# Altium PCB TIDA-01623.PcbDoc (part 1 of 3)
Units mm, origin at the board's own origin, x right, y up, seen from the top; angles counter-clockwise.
Board outline 77.73 x 42 mm, 4 copper layers (Top Layer, Signal Layer 1, Signal Layer 2, Bottom Layer), stack 0.651 mm thick; 213 components, 127 nets, 575 pads, 342 vias.
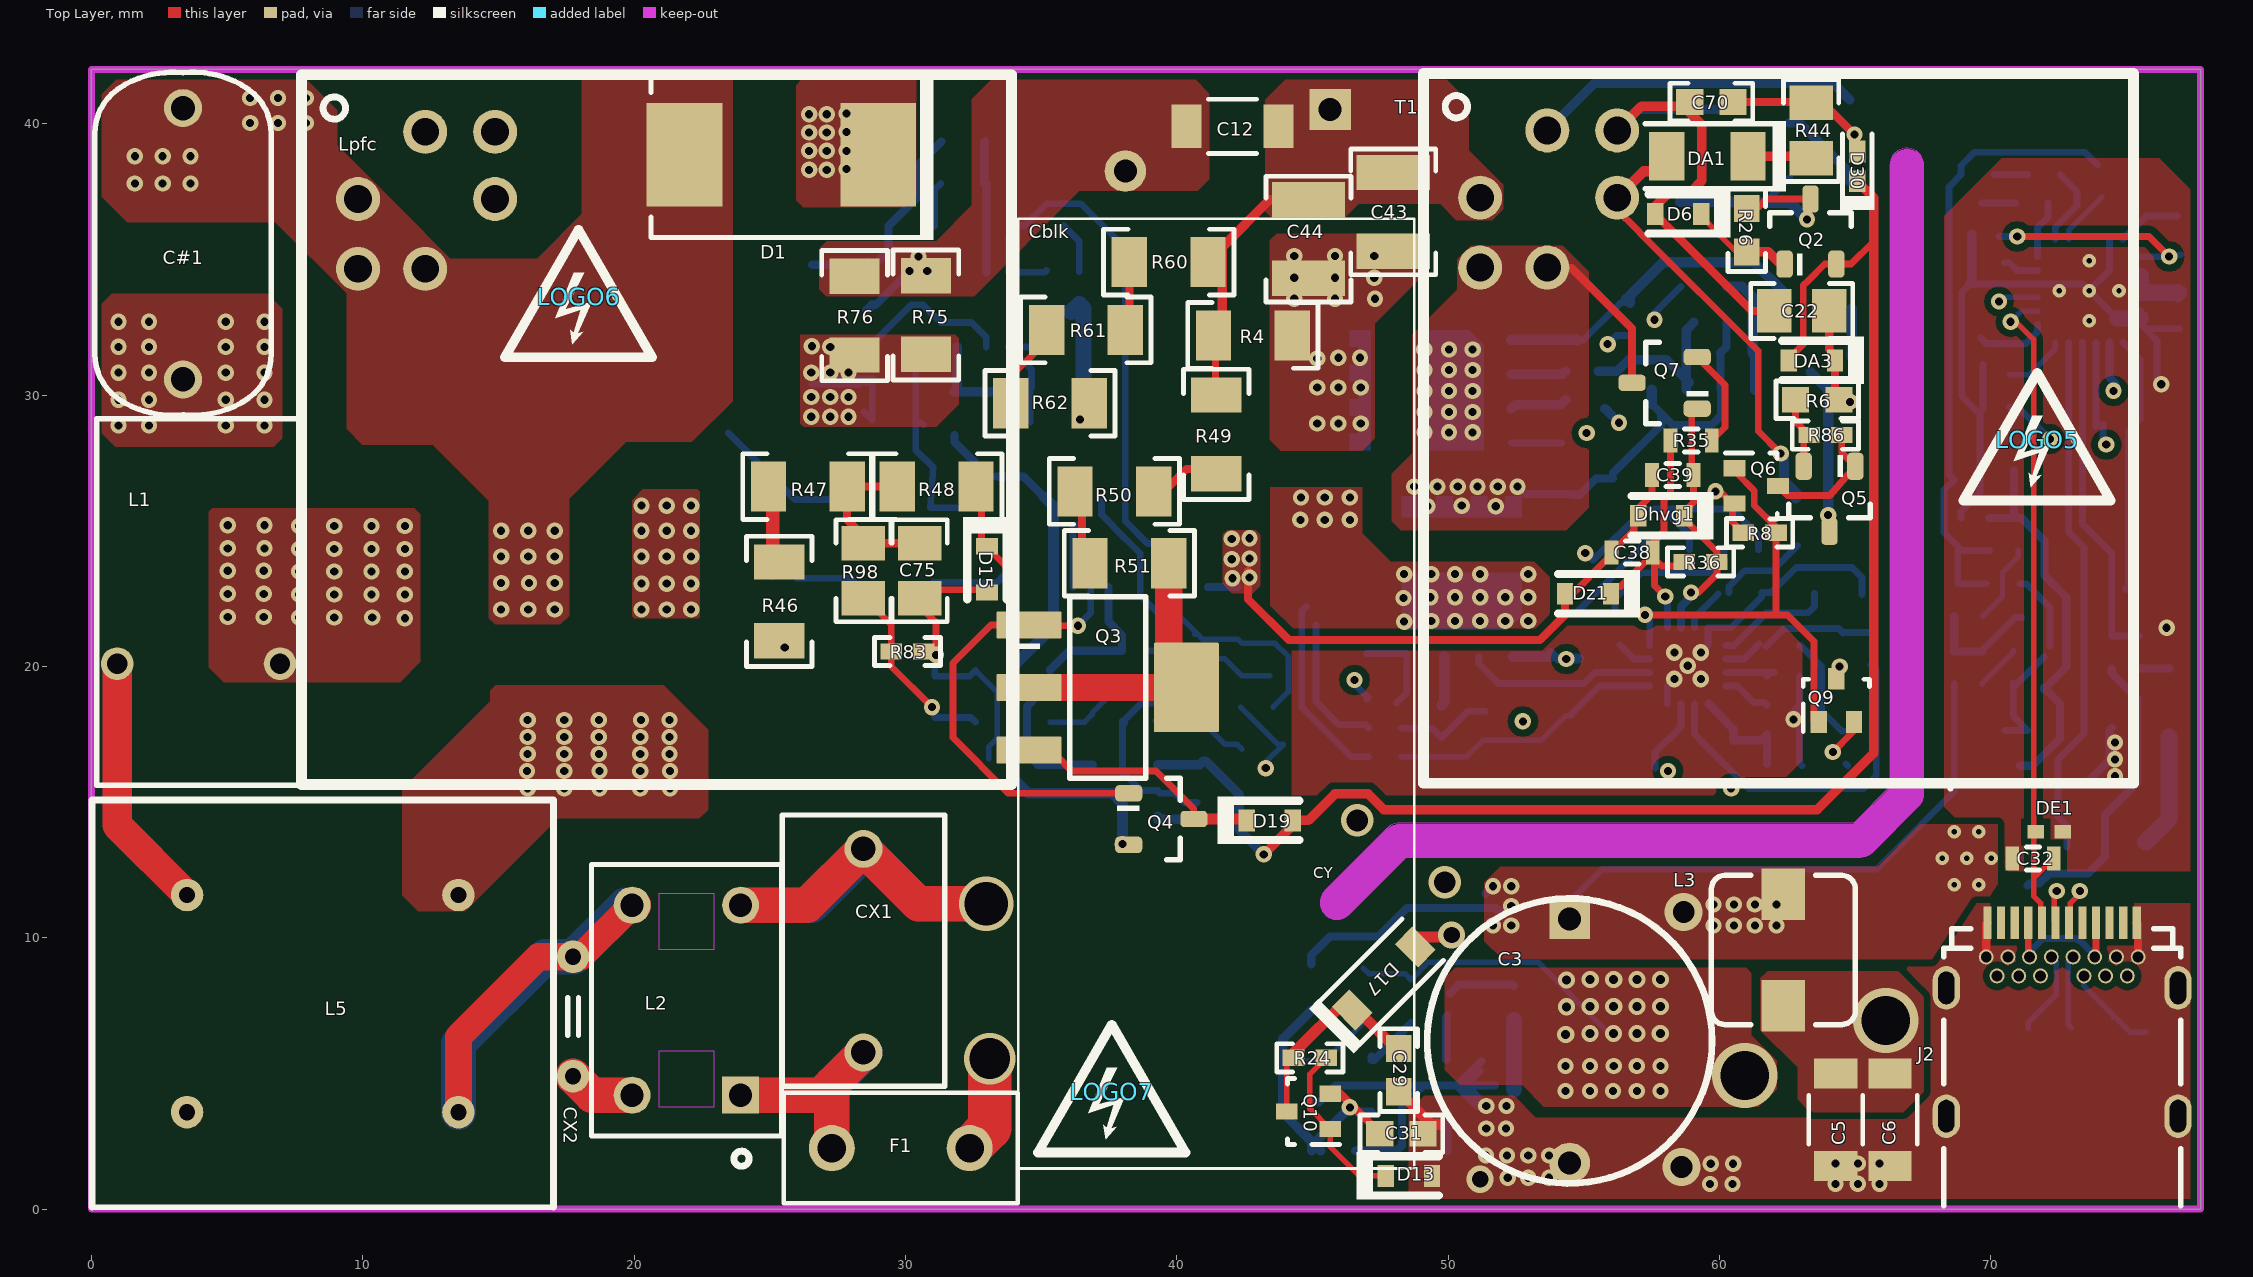
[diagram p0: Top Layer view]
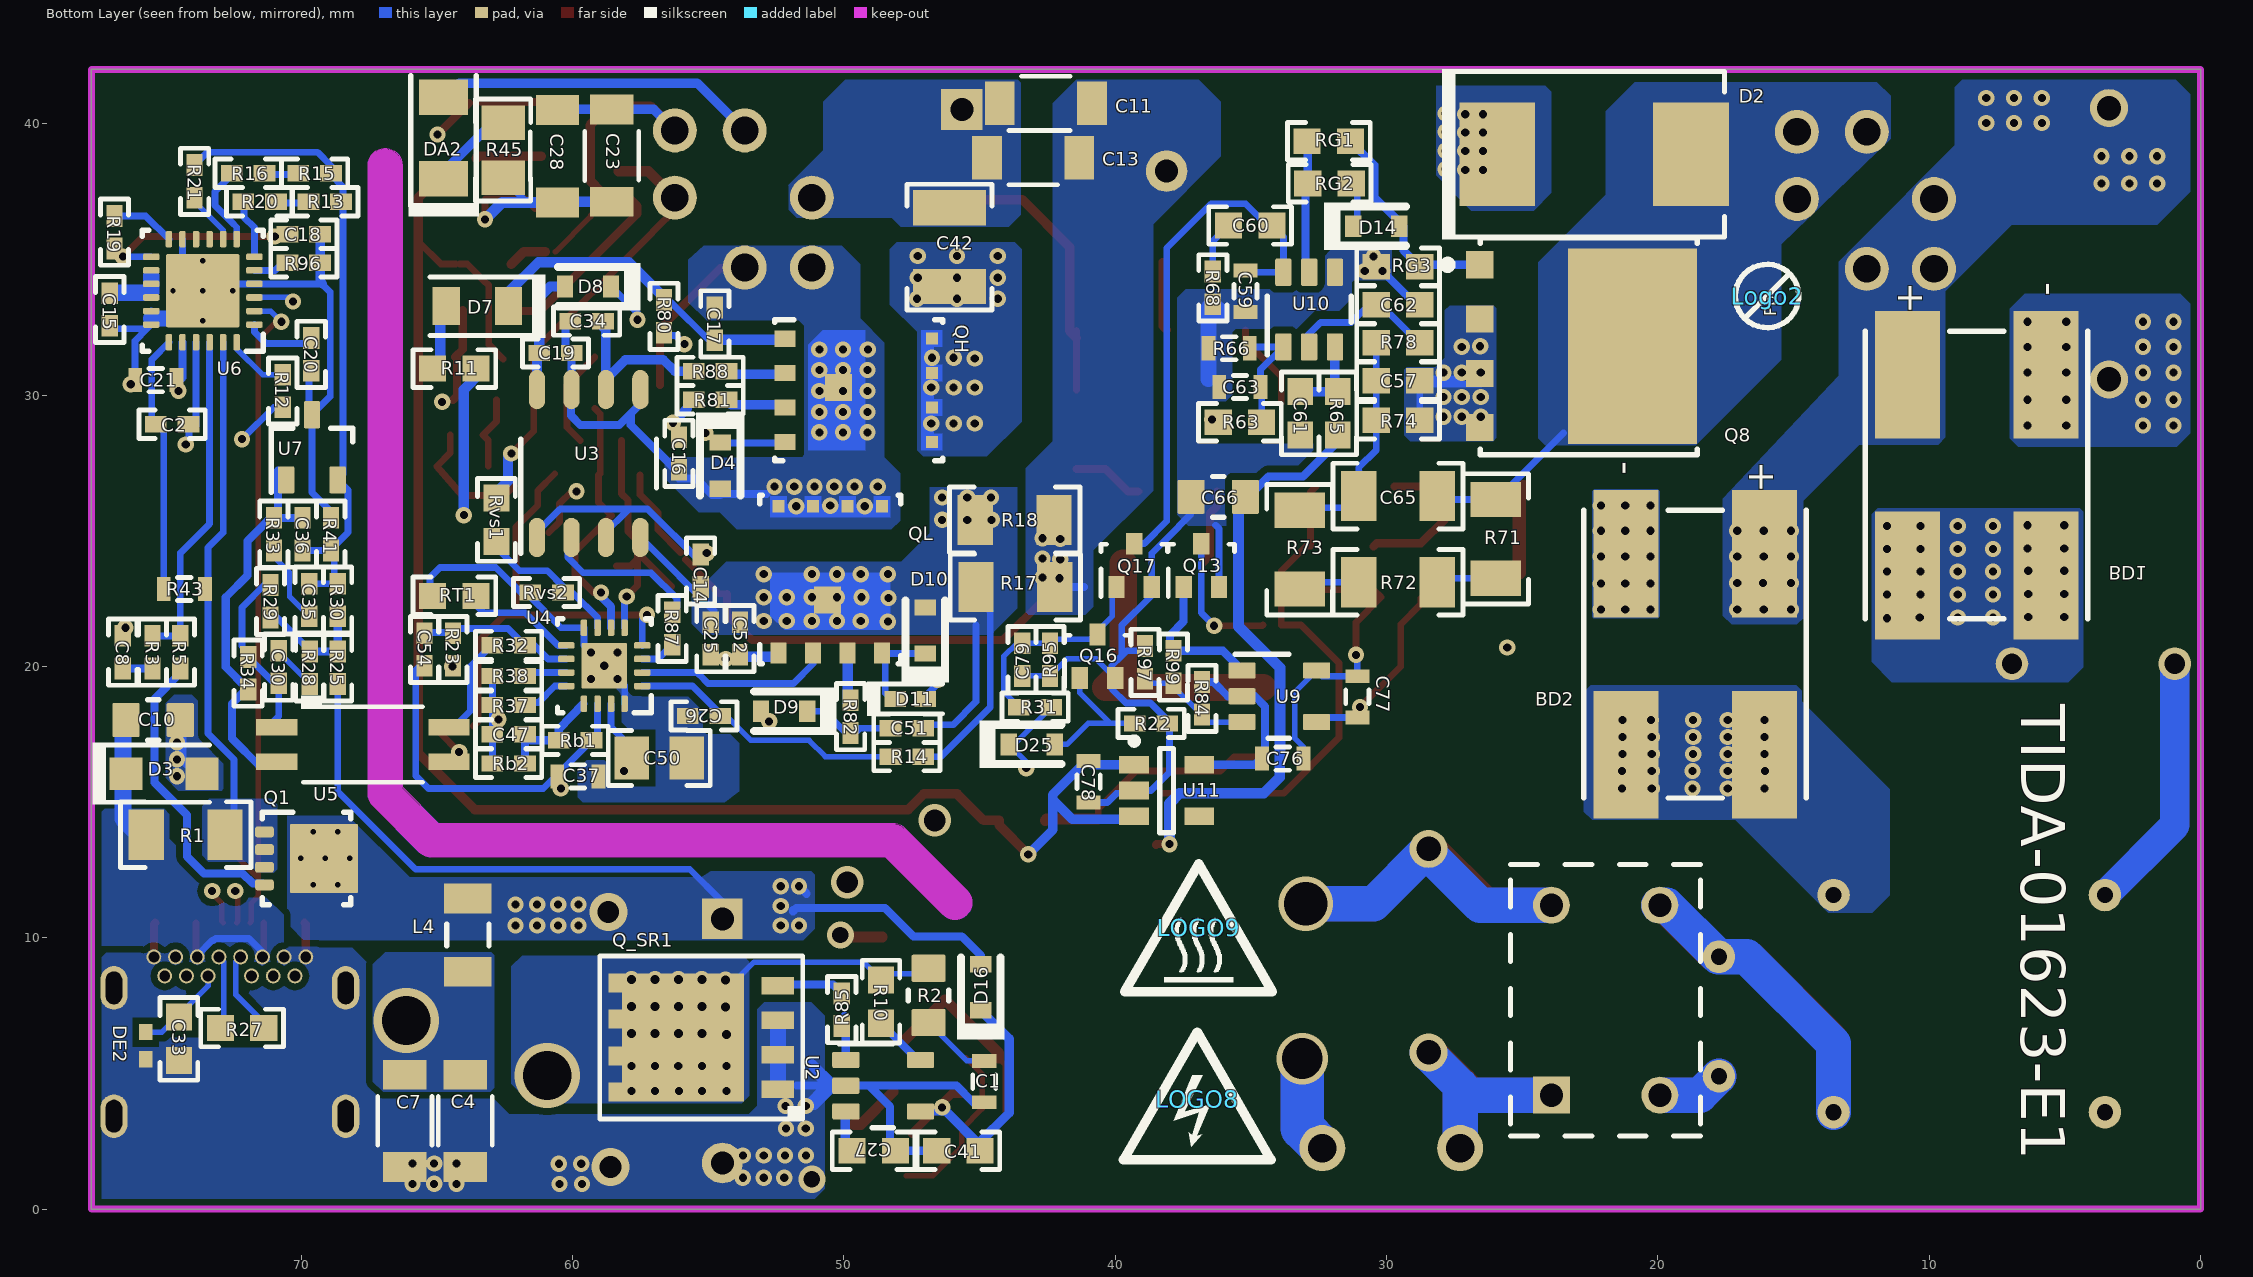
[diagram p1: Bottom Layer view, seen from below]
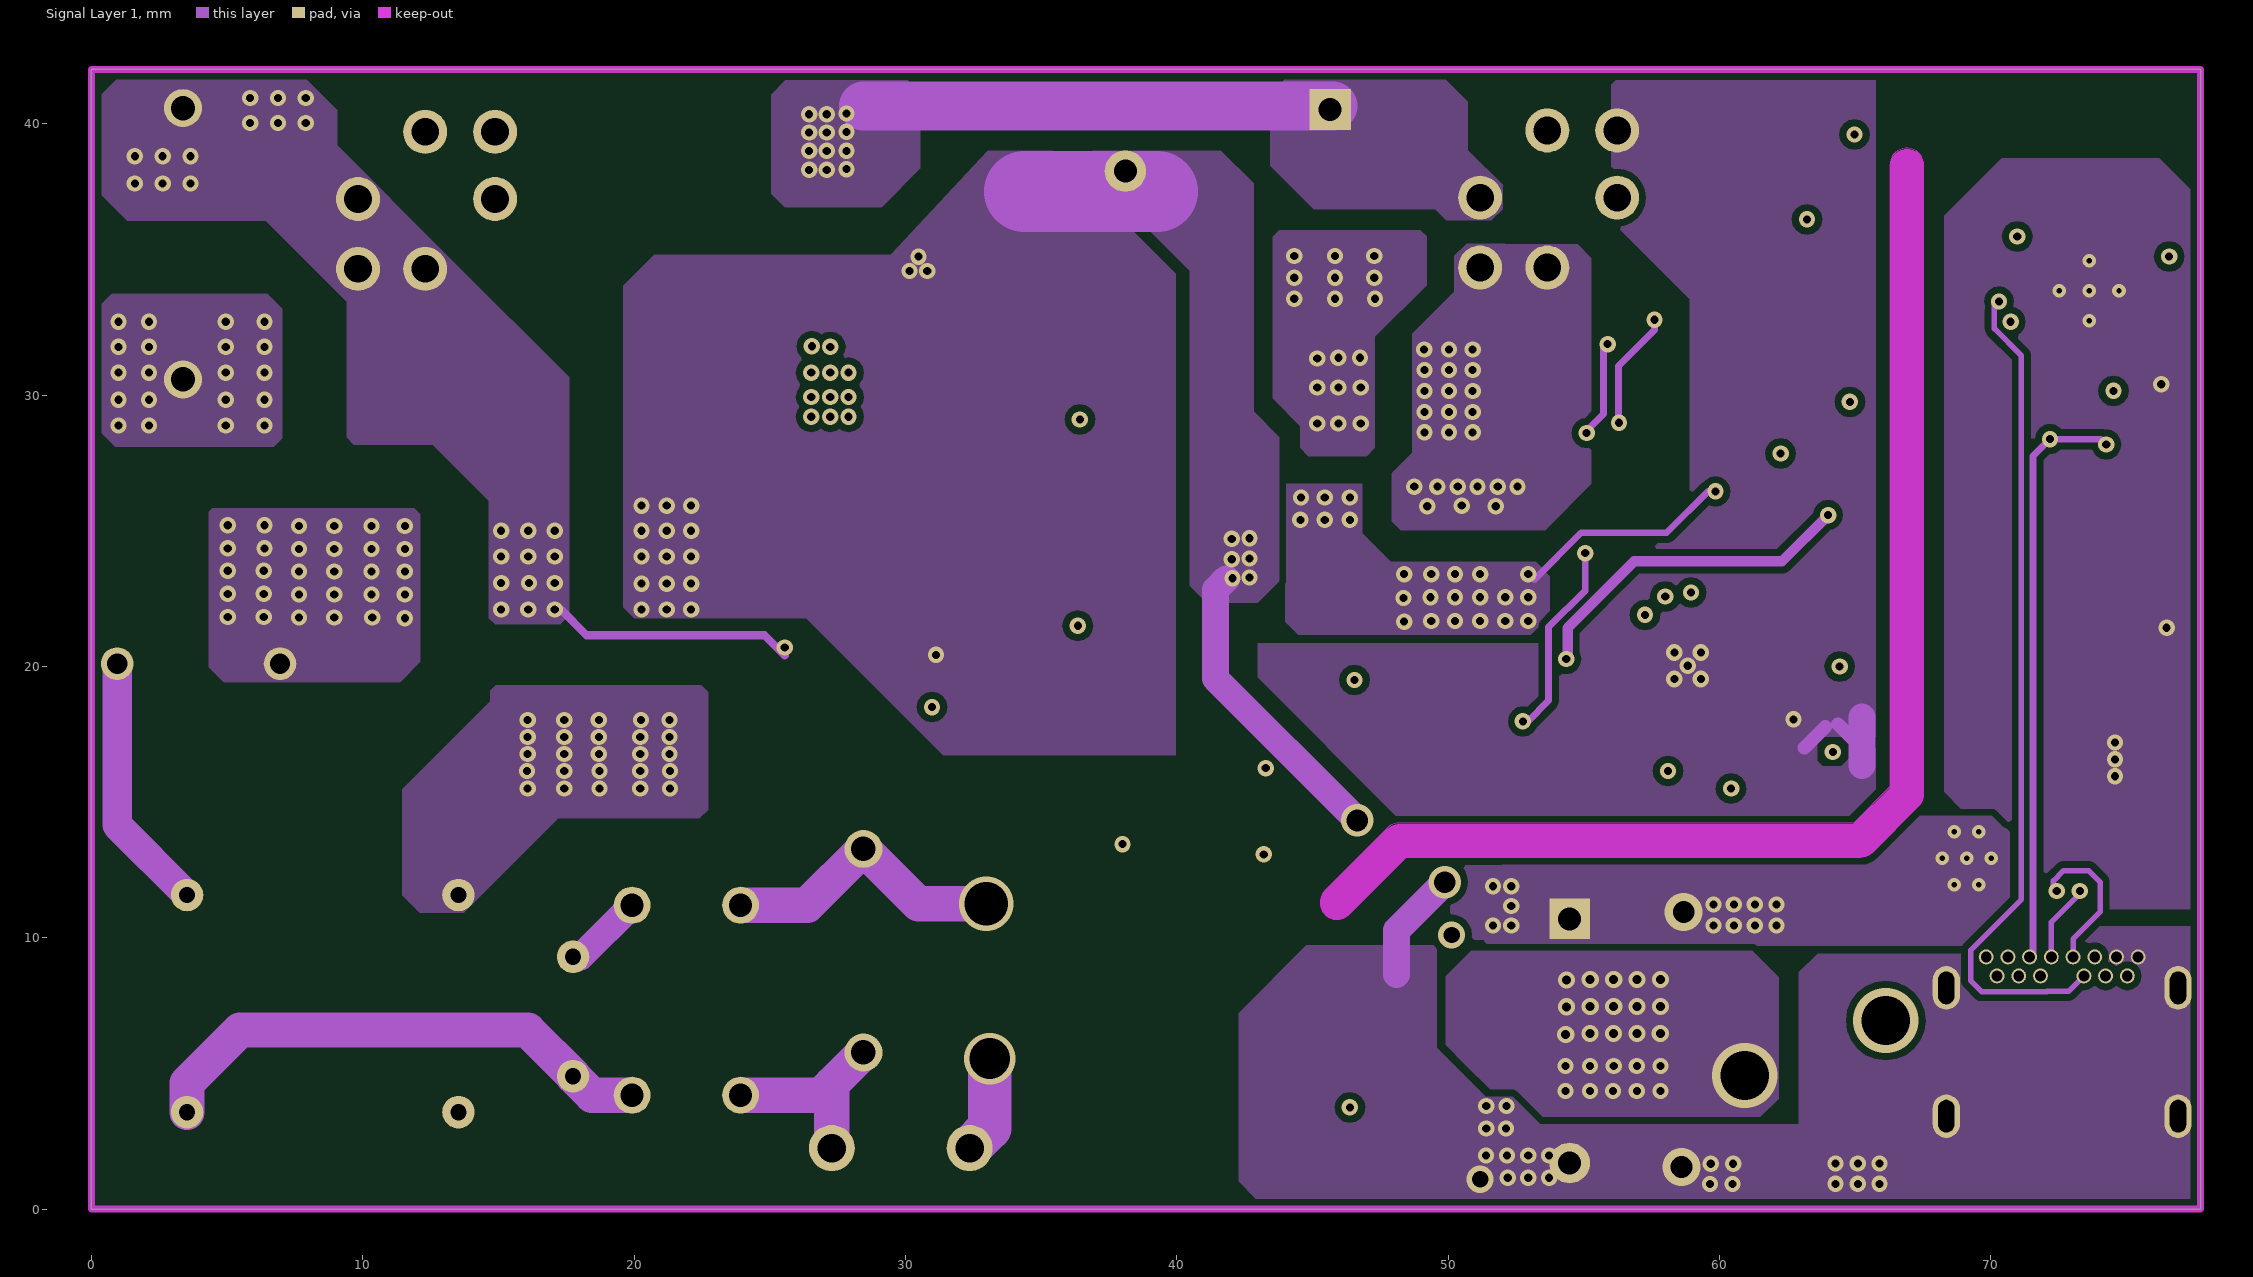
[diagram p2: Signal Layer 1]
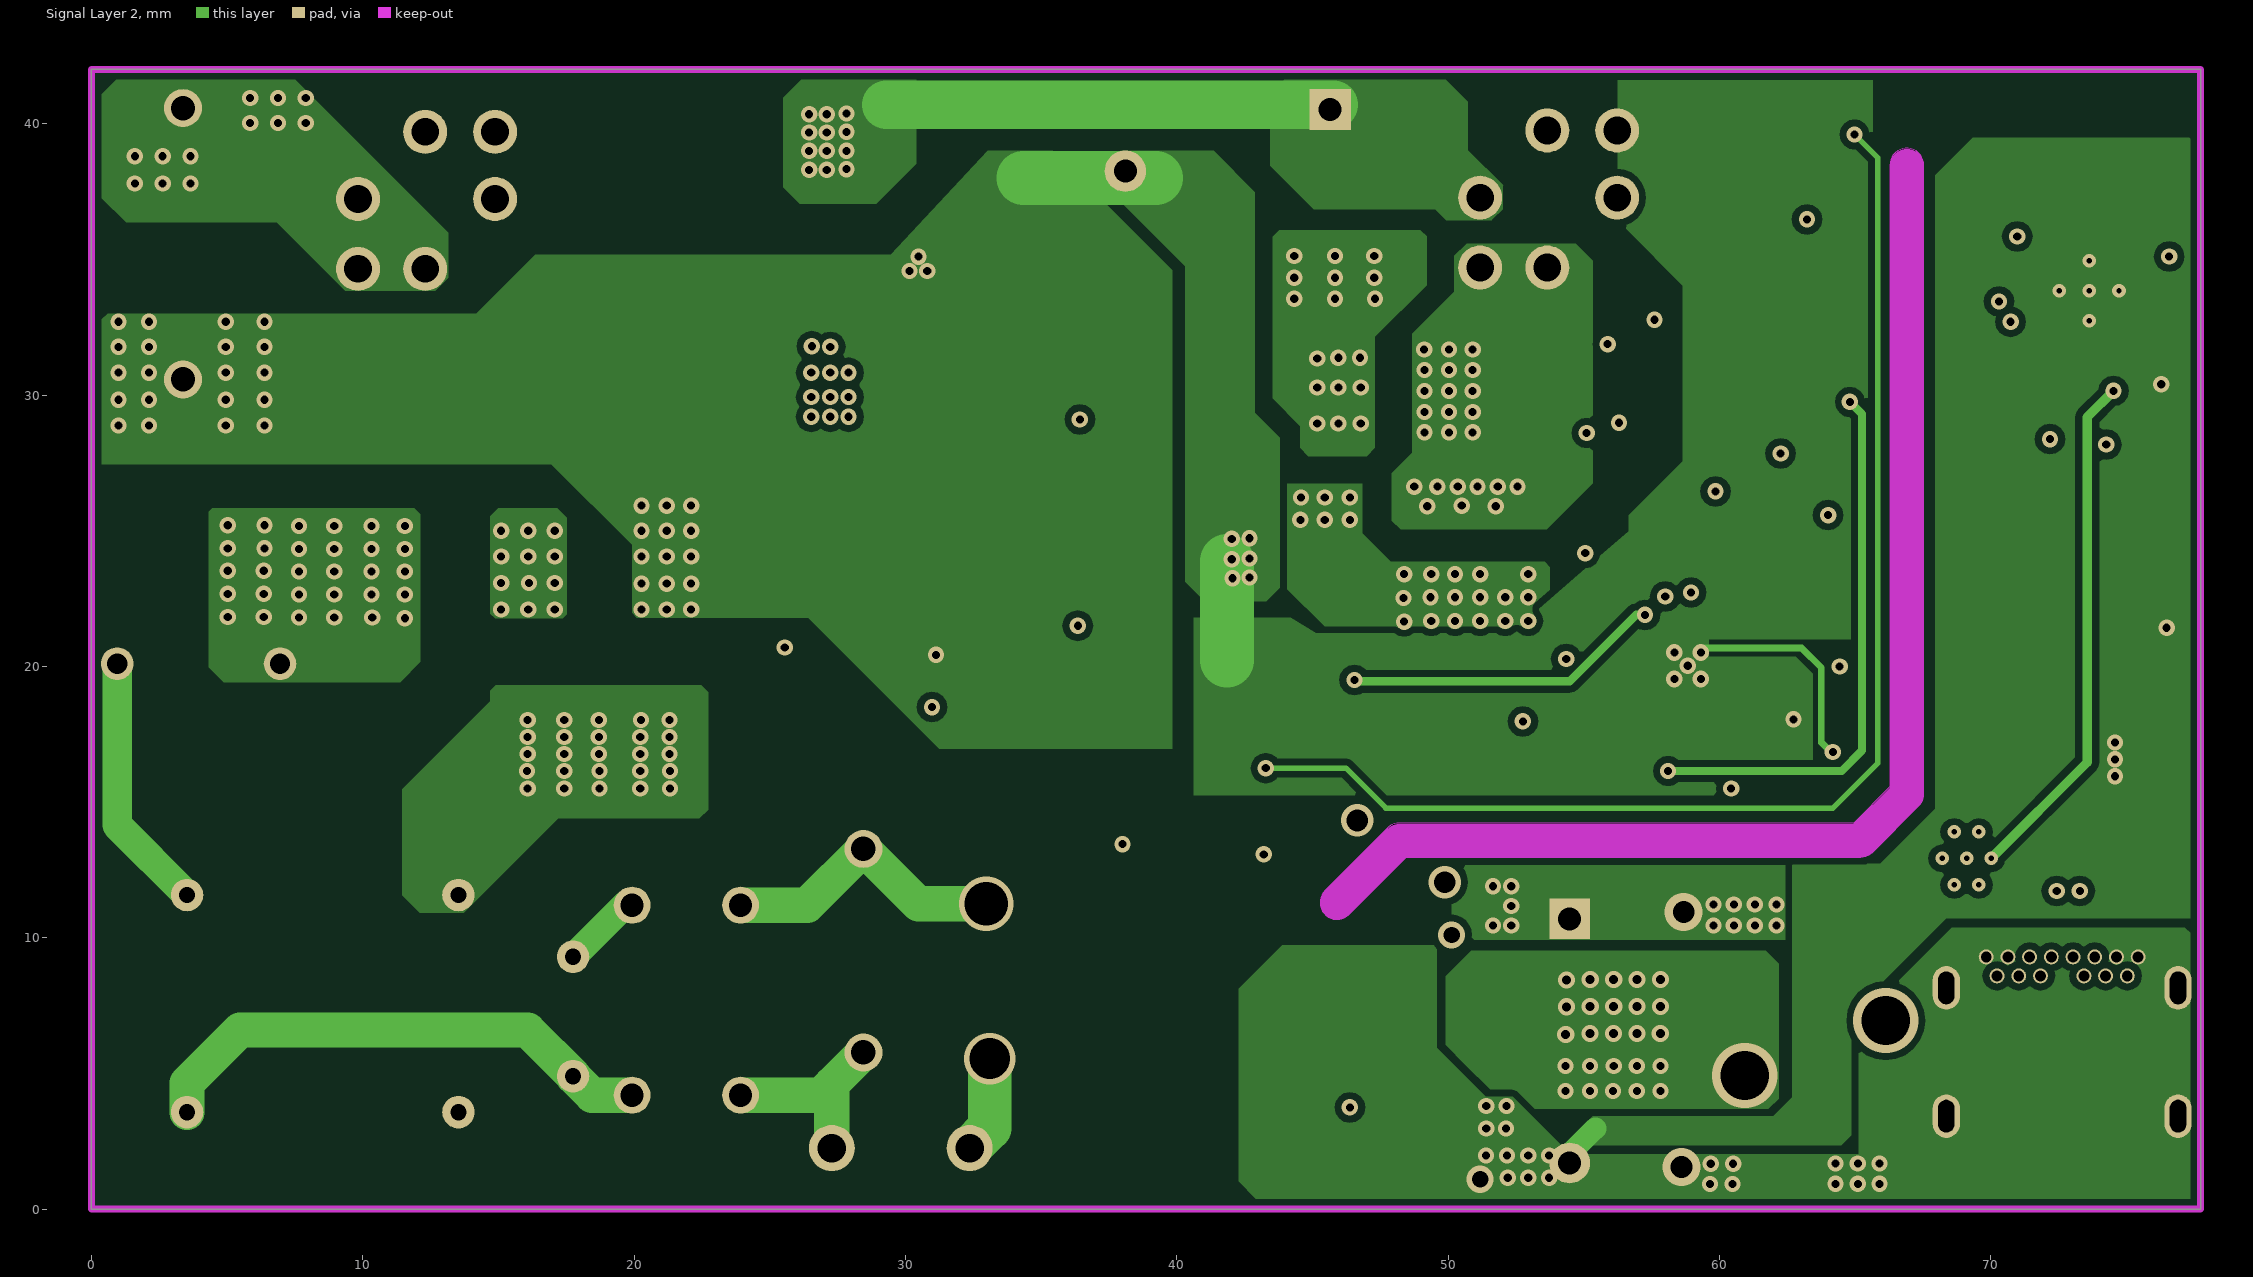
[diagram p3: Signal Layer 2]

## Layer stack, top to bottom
Top Solder: solder mask 0.0102, Solder Resist, Dk 3.5
Top Layer: signal copper 0.0356
Dielectric 1: prepreg 0.127, Dk 4.2
Signal Layer 1: signal copper 0.036
Dielectric 2: core 0.254, Dk 4.2
Signal Layer 2: signal copper 0.036
Dielectric 3: prepreg 0.127, Dk 4.2
Bottom Layer: signal copper 0.0356
Bottom Solder: solder mask 0.0102, Solder Resist, Dk 3.5

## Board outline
0,0 0,42 77.725,42 77.725,0
cut-out: 45.457,11.742 ccw(c45.9,11.3) 46.342,10.858 48.459,12.975 65.2,12.975 ccw(c65.2,13.6) 65.642,13.158 67.342,14.858 ccw(c66.9,15.3) 67.525,15.3 67.525,38.475 ccw(c66.9,38.475) 66.274,38.475 66.274,15.559 64.941,14.225 48.2,14.225 ccw(c48.2,13.6) 47.757,14.042

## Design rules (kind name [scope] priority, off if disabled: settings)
AcuteAngle [All] p1: minimum=4.50000000000000E+0001 checktracksonly=FALSE
AssemblyTestPointUsage [All] p1: valid=2
BoardOutlineClearance BoardOutlineClearance_MountingHoles [OnCopper and InComponentClass('Mounting Holes')] p1: gap=0.3
BoardOutlineClearance BoardOutlineClearance_Poly [OnCopper and IsPoly] p2: gap=0.3
BoardOutlineClearance [OnCopper and Not InComponentClass('Logo') and not InComponentClass('FiducialMark') and not InRegion(1000,500,4000,800) and not InPoly] p3: gap=0.3
Clearance Clearance_Keepouts [((IsTrack Or IsArc) And Not InPoly) And IsFree and IsKeepOut vs ((IsTrack Or IsArc) And Not InPoly) And IsFree and IsKeepOut] p1: gap=0.254
Clearance Clearance_Poly [InPolygon] p2: gap=0.254
Clearance [All] p3: gap=0.2
ComponentClearance ComponentClearance_MountingHoles_FiducialMarks [InComponentClass('Mounting Holes') vs InComponentClass('FiducialMark')] p1 off: gap=0.1 collisioncheckmode=3 verticalgap=0.1 showdistances=FALSE
ComponentClearance ComponentClearance_Shunt [InComponentClass('Header') vs InComponentClass('Shunt')] p2 off: gap=0 collisioncheckmode=3 verticalgap=0 showdistances=FALSE
ComponentClearance ComponentClearance_Logo [InComponentClass('Logo')] p3 off: gap=0.1 collisioncheckmode=3 verticalgap=0.1 showdistances=FALSE
ComponentClearance ComponentClearance_ScrewToNut [(HasFootprint('NY PMS 440 0025 PH')) vs (HasFootprint('Keystone_1902C'))] p4 off: gap=0.1 collisioncheckmode=3 verticalgap=0.1 showdistances=FALSE
ComponentClearance ComponentClearance_MountingHoles [InComponentClass('Mounting Holes')] p5 off: gap=0.1 collisioncheckmode=3 verticalgap=2540 showdistances=FALSE
ComponentClearance ComponentClearance_SmallPassives [HasFootprint('0201*') or HasFootprint('0402*') or HasFootprint('0508') or HasFootprint('0603*') or HasFootprint('0612') or HasFootprint('0805*') or HasFootprint('0815*') or HasFootprint('0830*') or HasFootprint('1206*') or HasFootprint('1210*') or HasFootprint('1808*') or HasFootprint('1812*') or HasFootprint('1825*') or HasFootprint('2010*') or HasFootprint('2220*') or HasFootprint('2225*') or HasFootprint('2512*') or HasFootprint('2728*') or HasFootprint('3518*') vs HasFootprint('0201*') or HasFootprint('0402*') or HasFootprint('0508') or HasFootprint('0603*') or HasFootprint('0612') or HasFootprint('0805*') or HasFootprint('0815*') or HasFootprint('0830*') or HasFootprint('1206*') or HasFootprint('1210*') or HasFootprint('1808*') or HasFootprint('1812*') or HasFootprint('1825*') or HasFootprint('2010*') or HasFootprint('2220*') or HasFootprint('2225*') or HasFootprint('2512*') or HasFootprint('2728*') or HasFootprint('3518*')] p6 off: gap=0.1 collisioncheckmode=3 verticalgap=0.1 showdistances=FALSE
ComponentClearance ComponentClearance_THtoSMT [IsThruComponent vs IsSMTComponent] p7 off: gap=0.1 collisioncheckmode=3 verticalgap=0.1 showdistances=FALSE
ComponentClearance ComponentClearance_THtoTH [IsThruComponent vs IsThruComponent] p8 off: gap=0.1 collisioncheckmode=3 verticalgap=0.1 showdistances=FALSE
ComponentClearance [All] p9 off: gap=0.1 collisioncheckmode=3 verticalgap=0.1 showdistances=FALSE
DiffPairsRouting [All] p1: maxlimit=2.54 minlimit=0.254 mostfreqgap=0.254 toplayer_minwidth=0.381 toplayer_maxwidth=0.381 toplayer_prefwidth=0.381 midlayer1_minwidth=0.381 midlayer1_maxwidth=0.381 midlayer1_prefwidth=0.381 midlayer2_minwidth=0.381 midlayer2_maxwidth=0.381 midlayer2_prefwidth=0.381 bottomlayer_minwidth=0.381 bottomlayer_maxwidth=0.381 bottomlayer_prefwidth=0.381 maxuncoupledlength=25.4
FabricationTestPointUsage TestPointUsage [All] p1: valid=2 allowmultiple=FALSE
FabricationTestpoint Testpoint [All] p1: side=3 testpointundercomponent=TRUE minsize=1.016 maxsize=2.54 preferedsize=1.524 minholesize=0 maxholesize=1.016 preferedholesize=0.813 testpointgrid=0.025 allowsidetop=TRUE allowsidebottom=TRUE usegrid=TRUE gridtolerance=0
FanoutControl Fanout_LCC [IsLCC] p1: bgadir=Out bgaviamode=Centered fanoutstyle=Auto fanoutdirection=Alternating viagrid=0.025 // Fanout_LCC (Default Rule)
FanoutControl Fanout_BGA [IsBGA] p2: bgadir=Out bgaviamode=Centered fanoutstyle=Auto fanoutdirection=Alternating viagrid=0.025 // Fanout_BGA (Default Rule)
FanoutControl Fanout_Default [All] p4: bgadir=Out bgaviamode=Centered fanoutstyle=Auto fanoutdirection=Alternating viagrid=0.025 // Fanout_Default (Default Rule)
FanoutControl Fanout_Small [(CompPinCount < 5)] p5: bgadir=Out bgaviamode=Centered fanoutstyle=Auto fanoutdirection=OutThenIn viagrid=0.025 // Fanout_Small (Default Rule)
HoleSize [All] p1: absolutevalues=TRUE maxlimit=0.3 minlimit=0.3 maxpercent=80.000 minpercent=20.000
MinimumAnnularRing MinimumAnnularRing_ThermalPadVias [IsVia and InAnyComponent] p1: minimumring=0.15
MinimumAnnularRing [All] p2: minimumring=0.025
MinimumSolderMaskSliver MinimumSolderMaskSliver_Logo [InComponentClass('Logo') vs InComponentClass('Logo')] p1: minsoldermaskwidth=0.018
MinimumSolderMaskSliver [All] p2: minsoldermaskwidth=0.1
PlaneClearance [All] p1: clearance=0.254
PlaneConnect [All] p1: planeconnectstyle=Direct reliefexpansion=0.254 reliefentries=4 reliefconductorwidth=0.254 reliefairgap=0.254
PolygonConnect [All] p1: connectstyle=Direct reliefconductorwidth=0.254 reliefentries=4 polygonreliefangle="90 Angle" airgapwidth=0.254
RoutingVias ThermalPadVias [IsVia and InAnyComponent] p1: holewidth=0.2 width=0.5 viastyle="Through Hole" minholewidth=0.2 minwidth=0.5 maxholewidth=0.33 maxwidth=0.6
RoutingVias [All] p2: holewidth=0.3 width=0.6 viastyle="Through Hole" minholewidth=0.3 minwidth=0.6 maxholewidth=2 maxwidth=3
SilkToBoardRegionClearance [Not ((IsComment or IsDesignator) And (Hide <> 'False')) and not InRegion(1000,500,4000,800)] p1:
SilkToSilkClearance SilkToSilkClearance_Pb-FreeLogo [(HasFootprint('Pb-Free_Overlay_Medium') OR HasFootprint('Pb-Free_Overlay_Small')) vs (HasFootprint('Pb-Free_Overlay_Medium') OR HasFootprint('Pb-Free_Overlay_Small'))] p1: silktosilkclearance=0
SilkToSilkClearance [All] p2: silktosilkclearance=0.102
SilkToSolderMaskClearance SilkToComponentPadClearance [(IsPad or IsFill or IsRegion) and InAnycomponent] p1: minsilkscreentomaskgap=0.127 clearancetoexposedcopper=TRUE
SilkToSolderMaskClearance "Silk to Solder Mask Opening" [All] p2: minsilkscreentomaskgap=0.102 clearancetoexposedcopper=FALSE
SolderMaskExpansion [All] p1: expansion=0.05
Width [All] p1: maxlimit=2.54 minlimit=0.152 preferedwidth=0.254 checkconnectedcopper=TRUE
14 further rules are at their usual default settings.

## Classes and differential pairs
component class TIDA-01623_PFC_Stage: BD1 BD2 C56 C57 C59 C60 C61 C62 C63 C65 C66 C75 C76 C77 C78 C79 C#1 Cblk CX1 CX2 D1 D2 D14 D15 D19 D25 F1 L1 L2 L5 Lpfc Q3 Q4 Q8 Q13 Q16 Q17 R22 R31 R46 R47 R48 R49 R50 R51 R60 R61 R62 R63 R65 R66 R68 R71 R72 R73 R74 R75 R76 R78 R83 R84 R95 R97 R98 R99 RG1 RG2 RG3 U9 U10 U11
component class TIDA-01623_Hardware: !PCB1 Logo2 LOGO5 LOGO6 LOGO7 LOGO8 LOGO9 LOGO10
component class TIDA-01623-ACF_Stage: C1 C2 C3 C4 C5 C6 C7 C8 C10 C11 C12 C13 C14 C15 C16 C17 C18 C19 C20 C21 C22 C23 C25 C26 C27 C28 C29 C30 C31 C32 C33 C34 C35 C36 C37 C38 C39 C41 C42 C43 C44 C47 C50 C51 C52 C54 C70 D3 D4 D5 D6 D7 D8 D9 D10 D11 D13 D16 D17 D30 DA1 DA2 DA3 DE1 DE2 Dhvg1 Dz1 J2 L3 L4 Q1 Q2 Q5 Q6 Q7 Q9 Q10 Q_SR1 QH QL R1 R2 R3 R4 R5 R6 R8 R10 R11 R12 R13 R14 R15 R16 R17 R18 R19 R20 R21 R23 R24 R25 R26 R27 R28 R29 R30 R32 R33 R34 R35 R36 R37 R38 R41 R43 R44 R45 R80 R81 R82 R85 R86 R87 R88 R96 Rb1 Rb2 RT1 Rvs1 Rvs2 T1 U2 U3 U4 U5 U6 U7

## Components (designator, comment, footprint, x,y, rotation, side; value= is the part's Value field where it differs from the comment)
BD1 "Z4DGP406L-HF" Z4-D#1 8.25,27.05 r270 bottom
BD2 "Z4DGP406L-HF" Z4-D#2 18.625,20.45 r270 bottom
C1 "GRM188R72E221KW07D" 0603S 44.825,4.7 r90 bottom
C2 "C1005X5R1A334K050BB" 0402 74.75,28.925 r0 bottom
C3 "APSG200ELL681MJB5S" PCBComponent_1#1 54.475,6.2 r270 top
C4 "C3216X5R1E336M160AC" 1206_180 63.95,3.25 r270 bottom
C5 "C3216X5R1E336M160AC" 1206_180 64.279,3.292 r270 top
C6 "C3216X5R1E336M160AC" 1206_180 66.279,3.292 r270 top
C7 "C3216X5R1E336M160AC" 1206_180 66.175,3.25 r270 bottom
C8 "C0402C103J5RACTU" 0402 76.575,20.525 r90 bottom
C10 "C2012X5R1E685K125AC" 0805_HV1 75.45,18.025 r180 bottom
C11 "C3216X7T2W104K160AA" 1206_180 42.55,40.75 r0 bottom
C12 "C3216X7T2W104K160AA" 1206_180 42.05,39.9 r0 top
C13 "C3216X7T2W104K160AA" 1206_180 43.025,38.75 r0 bottom
C14 "GRM155R71H223KA12D" 0402 55.275,23.525 r270 bottom
C15 "C1005X7R1H104K050BB" 0402 77.05,33.15 r270 bottom
C16 "GCM155R71H103KA55D" 0402 56.075,27.85 r270 bottom
C17 "GRM155R71H223KA12D" 0402 54.75,32.625 r90 bottom
C18 "C1005X5R1E224M050BC" 0402 69.9,35.925 r180 bottom
C19 "GRM155R71H223KA12D" 0402 60.622,31.549 r180 bottom
C20 "C1005X7R1H104K050BB" 0402 69.625,31.5 r270 bottom
C21 "C0603C104K5RACTU" 0603S 75.35,30.55 r0 bottom
C22 "C2012JB1V226M125AC" 0805_HV 63.025,33.1 r180 top
C23 "GRM31CZ72A475KE11" 1206_180 58.55,38.825 r90 bottom
C25 "GRM155R71H223KA12D" 0402 54.9,21.025 r90 bottom
C26 "GRM1555C1H220JA01D" 0402 55.15,18.175 r180 bottom
C27 "GRM188R61H225KE11D" 0603 48.9,2.15 r0 bottom
C28 "GRM31CZ72A475KE11" 1206_180 60.55,38.8 r90 bottom
C29 "UMK107AB7105KA-T" 0603 48.175,5.125 r90 top
C30 "GRM155R71H472KA01D" 0402 70.825,19.975 r270 bottom
C31 "UMK107AB7105KA-T" 0603 48.275,2.775 r0 top
C32 "GRM188R71H561KA01D" 0603S 71.55,12.925 r180 top
C33 "GRM188R71H561KA01D" 0603 74.5,6.275 r90 bottom
C34 "GRM1555C1H101JA01D" 0402 59.475,32.725 r180 bottom
C35 "C0402C103J5RACTU" 0402 69.7,22.45 r90 bottom
C36 "GRM1555C1H3R3CA01D" 0402 69.95,24.875 r90 bottom
C37 "GRM188R71H104KA93D" 0603S 59.8,15.95 r180 bottom
C38 "GRM1885C1H220JA01D" 0603S 56.775,24.2 r180 top
C39 "GRM1885C1H222JA01D" 0603S 58.275,27.05 r0 top
C41 "UMK107AB7105KA-T" 0603 45.775,2.15 r180 bottom
C42 "C3225X7T2E334K200AA" 1210_220 46.1,35.45 r90 bottom
C43 "C3225X7T2E334K200AA" 1210_220 47.975,36.75 r90 top
C44 "C3225X7T2E334K200AA" 1210_220 44.85,35.75 r90 top
C47 "GRM1555C1H221JA01D" 0402 62.35,17.5 r0 bottom
C50 "C2012X6S1H475K125AC" 0805_HV 56.8,16.625 r180 bottom
C51 "GCM155R71H103KA55D" 0402 47.675,17.725 r180 bottom
C52 "GRM155R71H223KA12D" 0402 53.825,21.025 r90 bottom
C54 "GRM1555C1H221JA01D" 0402 65.45,20.625 r90 bottom
C57 "GRM188R72A392KA01D" 0603 29.575,30.525 r180 bottom
C59 "GRM188R71H333KA61D" 0603S 35.2,33.825 r270 bottom
C60 "GRM188R71E105KA12D" 0603 35.025,36.25 r0 bottom
C61 "UMK107AB7105KA-T" 0603 33.175,29.325 r270 bottom
C62 "GRM1885C1H221JA01D" 0603 29.575,33.325 r0 bottom
C63 "GRM1885C1H222JA01D" 0603S 35.4,30.3 r180 bottom
C65 "VJ1206A100JXGAT5Z" 1206 29.575,26.275 r0 bottom
C66 "C0805C105K3RACTU" 0805_HV1 36.2,26.25 r0 bottom
C70 "GRM188R61H225KE11D" 0603 59.7,40.8 r180 top
C75 "C2012X7T2E104K125AA" 0805_HV 30.525,23.525 r270 top
C76 "UMK107AB7105KA-T" 0603S 33.825,16.6 r0 bottom
C77 "GRM1885C1H221JA01D" 0603S 31.075,18.875 r90 bottom
C78 "UMK107AB7105KA-T" 0603S 40.975,15.75 r90 bottom
C79 "GRM155R71E333KA88D" 0402 43.425,20.25 r270 bottom
C#1 "ECW-FD2W474Q1" ECWFD_1260x650x1270 3.375,35.575 r270 top locked
Cblk "420BXW68MEFC14.5X35" PCBComponent_1#2 34.15,36.5 r0 top locked
CX1 "0.068uF" WCAP-FTX2_10x6x12 28.45,9.525 r270 top
CX2 "275V AC, 220 nF" PCBComponent_1#3 17.75,7.1 r270 top
D1 "RS3K-E3/9AT" SMC 25.425,38.85 r180 top
D2 "MURS360T3G" SMC 22.35,38.875 r180 bottom
D3 "PMEG4030ER" SOD-123W 75.05,16.05 r180 bottom
D4 "CZRU52C6V2" SOD-523F 54.55,27.4 r270 bottom
D6 "CZRU52C16" SOD-523F 58.475,36.675 r180 top
D7 "RFU02VSM6S" RFU02VSM6S 63.5,33.275 r180 bottom
D8 "CZRU52C2" SOD-523F 59.425,34 r0 bottom
D9 "CZRU52C2" SOD-523F 52.2,18.35 r0 bottom
D10 "CZRU52C6V2" SOD-523F 47,21.325 r90 bottom
D11 "SDM03U40-7" SOD-523 47.55,18.8 r180 bottom
D13 "" SOD-523F 48.55,1.225 r0 top
D14 "CDBU0245" SOD-523F 30.375,36.225 r180 bottom
D15 "CZRU52C16" SOD-523F 33,23.575 r270 top
D16 "" SOD-523F 44.95,8.175 r90 bottom
D17 "RF071M2S" SOD-123 47.625,8.5 r45 top
D19 "CDBU0245" SOD-523F 43.425,14.325 r0 top
D25 "CZRU52C13" SOD-523F 43.075,17.125 r180 bottom
D30 "RB520S30,115" SOD-523 65.075,38.425 r90 top
DA1 "CSFMT108-HF" SOD-123H 59.55,38.8 r180 top
DA2 "CSFMT108-HF" SOD-123H 64.75,39.475 r90 bottom
DA3 "CDBU0245" SOD-523F 63.4,31.275 r180 top
DE1 "TPD1E05U06QDPYRQ1" DPY0002A 72.15,13.9 r180 top
DE2 "TPD1E05U06QDPYRQ1" DPY0002A 75.725,6.025 r90 bottom
Dhvg1 "CZRU52C24" SOD-523F 57.85,25.55 r180 top
Dz1 "CZRU52C20" SOD-523F 55.15,22.675 r180 top
F1 "40015000440" FUSE_392 29.825,2.25 r0 top
J2 "632 723 300 011" Wurth_632_723_300_011 72.625,-0.025 r0 top
L1 "WE-FI, 7447031" PCBComponent_1#4 3.95,20.1 r0 top
L2 "750343092" 750311982 21.925,7.7 r90 top
L3 "744316100" WE-HCI_5040 62.35,9.55 r180 top
L4 "74479136" 1206L 63.85,10.1 r90 bottom
L5 "750344166" PCBComponent_1#5 8.525,7.575 r180 top
Logo2 "Pb-Free Symbol" Pb-Free_Overlay_Small 15.975,33.65 r90 bottom
LOGO5 "DANGER HIGH VOLTAGE" IEC_HighVoltage_Small 71.7,28.35 r0 top
LOGO6 "DANGER HIGH VOLTAGE" IEC_HighVoltage_Small 17.95,33.625 r0 top
LOGO7 "DANGER HIGH VOLTAGE" IEC_HighVoltage_Small 37.6,4.325 r0 top
LOGO8 "DANGER HIGH VOLTAGE" IEC_HighVoltage_Small 36.975,4.05 r180 bottom
LOGO9 "CAUTION HOT SURFACE" IEC_HotSurface_Small 36.925,10.375 r180 bottom
Lpfc "340uH" RM4_5754 20.825,28.725 r0 top locked
Q1 "CSD17575Q3" DNH0008A 69.8,12.925 r180 bottom
Q2 "AP10TN135N" SOT-23 63.35,36.025 r90 top
Q3 "STN1NK60Z" SOT-223 37.45,19.225 r0 top
Q4 "2N7002" SOT-23 39.425,14.375 r0 top
Q5 "DMP510DL" SOT-23 64.05,26.175 r270 top
Q6 "2N7002KW" SOT-323 61.35,26.65 r0 top
Q7 "BSS126 H6906" SOT-23 57.975,30.45 r180 top
Q8 "PartNumber" INF-PG-VSON-4 23.75,31.8 r270 bottom
Q9 "2N7002KW" SOT-323 64.3,18.75 r90 top
Q10 "BSS123W-7-F" SOT-323 44.85,3.6 r180 top
Q13 "2N7002KW" SOT-323 36.825,23.725 r90 bottom
Q16 "2N7002KW" SOT-323 40.65,20.375 r90 bottom
Q17 "2N7002KW" SOT-323 39.3,23.725 r90 bottom
Q_SR1 "BSC093N15NS5ATMA1" PG-TDSON-8 55.25,6.325 r0 bottom
QH "NV6115" PQFN8_5x6 49.45,30.175 r180 bottom locked
QL "nv6115" PQFN8_5x6 50.5,23.2 r90 bottom locked
R1 "WSL12065L000FEA" 1206 74.25,13.8 r0 bottom
R2 "ERJ-6GEYJ220V" 0805_HV1 46.875,7.875 r270 bottom
R3 "CRCW04021K00FKED" 0402 75.475,20.525 r90 bottom
R4 "CRCW12062M21FKEA" 1206 42.8,32.2 r180 top
R5 "CRCW040210R0FKED" 0402 74.45,20.525 r270 bottom
R6 "CRCW060310R0FKEA" 0603 63.6,29.825 r180 top
R8 "CRCW0402100KFKED" 0402 61.475,24.925 r0 top
R10 "RC0603FR-07100RL" 0603 48.625,7.65 r90 bottom
R11 "CRCW06035R11FKEA" 0603 64.35,30.975 r180 bottom
R12 "CRCW0402100RFKED" 0402 70.675,30.15 r270 bottom
R13 "RC0402JR-070RL" 0402 69.125,37.125 r0 bottom
R14 "CRCW0402825RFKED" 0402 47.675,16.675 r180 bottom
R15 "CRCW04022K00FKED" 0402 69.5,38.175 r0 bottom
R16 "CRCW040290K9FKED" 0402 71.95,38.175 r0 bottom
R17 "ERJ-8RQFR22V" 1206 43.675,22.925 r0 bottom
R18 "ERJ-8RQFR22V" 1206 43.7,25.4 r0 bottom
R19 "CRCW04020000Z0ED" 0402 76.875,36 r270 bottom
R20 "CRCW040261K9FKED" 0402 71.525,37.125 r0 bottom
R21 "CRCW040275K0FKED" 0402 73.925,37.875 r90 bottom
R22 "CRCW040210K0FKED" 0402 38.675,17.9 r180 bottom
R23 "CRCW0402432KFKED" 0402 64.4,20.625 r90 bottom
R24 "CRCW040249K9FKED" 0402 44.9,5.575 r0 top
R25 "CRCW040210R0FKED" 0402 68.65,19.95 r270 bottom
R26 "HV" 0603 61,36.075 r90 top
R27 "RC0603FR-07100RL" 0603 72.175,6.675 r180 bottom
R28 "CRCW0402562RFKED" 0402 69.675,19.95 r90 bottom
R29 "CRCW040210K0FKED" 0402 71.125,22.4 r270 bottom
R30 "CRCW0402150KFKED" 0402 68.65,22.45 r270 bottom
R31 "CRCW0402100KFKED" 0402 42.95,18.5 r0 bottom
R32 "CRCW040230K1FKED" 0402 62.35,20.775 r0 bottom
R33 "CRCW040256K2FKED" 0402 71,24.875 r270 bottom
R34 "CRCW040215K0FKED" 0402 71.95,19.75 r90 bottom
R35 "CRCW0603121RFKEA" 0603S 58.95,28.325 r0 top
R36 "RC0402FR-071ML" 0402 59.3,23.85 r0 top
R37 "CRCW0402150KFKED" 0402 62.35,18.575 r0 bottom
R38 "CRCW0402274KFKED" 0402 62.35,19.65 r180 bottom
R41 "CRCW0402150KFKED" 0402 68.9,24.875 r270 bottom
R43 "CRCW060324R9FKEA" 0603S 74.3,22.85 r180 bottom
R44 "RC0805FR-071RL" 0805_HV 63.375,39.75 r270 top
R45 "RC0805FR-071RL" 0805_HV 62.55,39.025 r90 bottom
R46 "CRCW12063M24FKEA" 1206 25.35,22.4 r270 top
R47 "CRCW12063M24FKEA" 1206 26.4,26.625 r180 top
R48 "CRCW12063M24FKEA" 1206 31.15,26.625 r180 top
R49 "CRCW12061K00FKEA" 1206 41.45,28.55 r270 top
R50 "CRCW12061K00FKEA" 1206 37.7,26.45 r180 top
R51 "CRCW12061K00FKEA" 1206 38.25,23.8 r0 top
R60 "CRCW12063M24FKEA" 1206 39.7,34.9 r0 top
R61 "CRCW12063M24FKEA" 1206 36.65,32.4 r0 top
R62 "CRCW12063M24FKEA" 1206 35.325,29.7 r180 top
R63 "CRCW0603274KFKEA" 0603 35.4,29 r0 bottom
R65 "CRCW06032R00FKEA" 0603 31.8,29.325 r270 bottom
R66 "CRCW060364K9FKEA" 0603S 35.8,31.725 r180 bottom
R68 "CRCW0402182KFKED" 0402 36.4,33.95 r90 bottom
R71 "CRCW12063M24FKEA" 1206 25.975,24.7 r90 bottom
R72 "CRCW12063M24FKEA" 1206 29.575,23.1 r180 bottom
R73 "CRCW12063M24FKEA" 1206 33.2,24.3 r270 bottom
R74 "RT0603DRE0724K3L" 0603 29.575,29.075 r0 bottom
R75 "ERJ-8RQFR22V" 1206 30.75,32.95 r270 top
R76 "ERJ-8RQFR22V" 1206 28.125,32.925 r270 top
R78 "CRCW0603750RFKEA" 0603 29.575,31.925 r0 bottom
R80 "CRCW040247K5FKED" 0402 56.625,32.9 r90 bottom
R81 "CRCW040210R0FKED" 0402 54.925,29.825 r0 bottom
R82 "CRCW0402100RFKED" 0402 49.75,18.15 r270 bottom
R83 "CRCW0402178KFKED" 0402 30.075,20.55 r0 top
R84 "CRCW0402100KFKED" 0402 36.8,18.825 r90 bottom
R85 "CRCW04020000Z0ED" 0402 50.075,7.35 r270 bottom
R86 "CRCW040230K1FKED" 0402 63.9,28.525 r180 top
R87 "CRCW040210R0FKED" 0402 56.325,21.4 r90 bottom
R88 "CRCW040210R0FKED" 0402 54.925,30.875 r180 bottom
R95 "CRCW0402100KFKED" 0402 42.4,20.25 r270 bottom
R96 "CRCW04020000Z0ED" 0402 69.9,34.875 r180 bottom
R97 "CRCW040239K2FKED" 0402 38.9,20.15 r270 bottom
R98 "CRCW08053M16FKEA" 0805_HV 28.45,23.525 r90 top
R99 "CRCW0402100KFKED" 0402 37.85,19.975 r270 bottom
Rb1 "CRCW0402332KFKED" 0402 59.9,17.275 r180 bottom
Rb2 "CRCW040256K2FKED" 0402 62.35,16.425 r180 bottom
RG1 "CRCW060310R0FKEA" 0603 32.125,39.35 r180 bottom
RG2 "CRCW06031R00FKEA" 0603 32.1,37.8 r180 bottom
RG3 "CRCW060382K5FKEA" 0603 29.575,34.725 r180 bottom
RT1 "NCP18WB473F10RB" 0603 64.35,22.6 r180 bottom
Rvs1 "ERJPA3F7502V" 0603 62.8,25.4 r90 bottom
Rvs2 "CRCW040212K4FKED" 0402 60.95,22.725 r180 bottom
T1 "750315856" RM4_5754 62.175,28.775 r0 top locked
U2 "UCC24612-1DBVR" DBV0005A_N 48.55,4.55 r180 bottom
U3 "ISO7710FD" D0008A_N 59.4,27.475 r90 bottom
U4 "UCC28780RTER" UCC28780 58.825,20.025 r180 bottom
U5 "FODM8801AV" MFP04A 67.725,17.125 r180 bottom
U6 "TPS25740BRGER" RGE0024H 73.62,33.845 r0 bottom
U7 "ATL431BQDBZR" DBZ0003A_N 69.6,28.075 r90 bottom
U9 "LMC7111BIM5" DBV0005A_N 33.95,18.9 r180 bottom
U10 "UCC28056DBV" DBV0006A_N 32.85,33.15 r90 bottom
U11 "LP2981AIM5-5.0" MF05A_N 38.1,15.425 r180 bottom

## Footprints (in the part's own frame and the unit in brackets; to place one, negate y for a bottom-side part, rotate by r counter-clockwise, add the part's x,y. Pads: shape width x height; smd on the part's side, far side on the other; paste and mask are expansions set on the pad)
0402 [mm] "0402 from SM-752 data"
  rect 0.8x0.6 smd: 1(-0.6,0) 2(0.6,0)
  silkscreen extent -1.22,-0.52 1.22,0.52, body extent -0.55,-0.3 0.55,0.3, height 0.6
0603 [mm] "0603 from SM-752 data"
  rect 1x0.95 smd: 1(-0.8,0) 2(0.8,0)
  silkscreen extent -1.52,-0.69 1.52,0.69, body extent -0.87,-0.47 0.87,0.47, height 1
0603S [mil]
  rect 20x35 smd: 1(-30,0) 2(30,0)
  silkscreen extent -10,-17 10,17, body extent -34,-19 34,19, height 39
0805_HV [mil] "0805 with 30mil clearance between pads"
  rect 50x63 smd: 1(-40,0) 2(40,0)
  silkscreen extent -74,-40 74,40, body extent -43,-29 43,29, height 57
0805_HV1 [mm] "Custom footprint based on analyzing multiple manufacturer recommendations"
  rrect10% 1x1.25 smd: 1(-1,0) 2(1,0)
  silkscreen extent -0.2,-0.75 0.2,0.75, body extent -1.1,-0.72 1.1,0.73, height 1.45
1206 [mm] "1206 from SM-752 data"
  rect 1.3x1.85 smd: 1(-1.45,0) 2(1.45,0)
  silkscreen extent -2.4,-1.21 2.4,1.21, body extent -1.7,-0.9 1.7,0.9, height 1.35
1206_180 [mm] "1206_180"
  rect 1.1x1.6 smd: 1(-1.7,0) 2(1.7,0)
  silkscreen extent -0.9,-1 0.9,1, body extent -1.75,-0.95 1.75,0.95, height 1.8
1206L [mm] "1206 from SM-752 data"
  rect 1.1x1.75 smd: 1(-1.35,0) 2(1.35,0)
  silkscreen extent -0.4,-0.77 0.4,0.77, body extent -1.7,-0.9 1.7,0.9, height 1.35
1210_220 [mm] "1210"
  rect 1.3x2.7 smd: 1(-1.45,0) 2(1.45,0)
  silkscreen extent -2.32,-1.57 2.32,1.57, body extent -1.7,-1.35 1.7,1.35, height 2.2
750311982 [mm] "4 LEAD,TH"
  rect 1.362x1.362 / inner round 1.362 / far side rect 1.362x1.362 hole 0.854: 1(-3.5,-2)
  round 1.362 hole 0.854: 2(-3.5,2) 3(3.5,2) 4(3.5,-2)
  Top Layer keep-out region: 1.873,-1.027 3.927,-1.027 3.927,1.027 1.873,1.027
  Top Layer keep-out region: -3.927,-1.027 -1.873,-1.027 -1.873,1.027 -3.927,1.027
  silkscreen extent -6.12,-3.5 5,3.5, body extent -5,-3.5 5,3.5, height 6.8
D0008A_N [mm] "SOIC, 8-Leads, Body 4.9x3.9mm, Pitch 1.27mm, IPC Medium Density"
  oval 1.45x0.6 smd: 1(-2.725,1.905) 2(-2.725,0.635) 3(-2.725,-0.635) 4(-2.725,-1.905) 5(2.725,-1.905) 6(2.725,-0.635) 7(2.725,0.635) 8(2.725,1.905)
  silkscreen extent -3.3,-2.5 0.9,2.5, body extent -3,-2.45 3,2.45, height 1.63
DBV0005A_N [mm] "SOT23, 5-Leads, Body 2.9x1.6mm, Pitch 0.95mm, Lead Span 2.8mm, IPC Medium Density"
  rrect17% 1x0.6 smd: 1(-1.375,0.95) 2(-1.375,0) 3(-1.375,-0.95) 4(1.375,-0.95) 5(1.375,0.95)
  silkscreen extent -1.63,-1.55 0.38,1.55, body extent -1.42,-1.46 1.42,1.46, height 1.09
DBV0006A_N [mm] "SOT23, 6-Leads, Body 2.9x1.6mm, Pitch 0.95mm, Lead Span 2.8mm, IPC Medium Density"
  rrect17% 1x0.6 smd: 1(-1.375,0.95) 2(-1.375,0) 3(-1.375,-0.95) 4(1.375,-0.95) 5(1.375,0) 6(1.375,0.95)
  silkscreen extent -1.68,-1.55 0.5,1.55, body extent -1.42,-1.46 1.42,1.46, height 1.12
DBZ0003A_N [mm] "SOT23, 3-Leads, Body 2.9x1.3mm, Pitch 0.95mm, Lead Span 2.4mm, IPC Medium Density"
  rrect17% 1x0.6 smd: 1(-1.2,0.95) 2(-1.2,-0.95) 3(1.2,0)
  silkscreen extent -1.65,-1.5 0.7,1.5, body extent -1.26,-1.46 1.26,1.46, height 0.98
DNH0008A [mm] "8 pin VSONP, 0.65 mm pitch"
  rrect50% 0.7x0.4 smd paste-0.05 mask-0.05: 1(-1.55,0.975) 2(-1.55,0.325) 3(-1.55,-0.325) 4(-1.55,-0.975) 5(1.55,-0.975) 6(1.55,-0.325) 7(1.55,0.325) 8(1.55,0.975)
  rrect14% 0.705x1.125 on Bottom Paste: 9(-0.208,-0.663) 9(-0.208,0.662) 9(0.697,-0.663) 9(0.697,0.662)
  rrect6% 1.775x2.45 on Bottom Solder: 9(0.327,0)
  rrect4% 2.51x2.55 smd paste-1.5 mask-1.5: 9(0.645,0)
  rect 0.5x0.3 on Bottom Solder: 9(1.175,-0.975) 9(1.175,-0.325) 9(1.175,0.325) 9(1.175,0.975)
  silkscreen extent -1.62,-1.7 1.62,1.7, body extent -1.65,-1.65 1.65,1.66, height 0.91
DPY0002A [mm] "R-PX2SON-N2"
  rect 0.6x0.5 smd: 1(-0.5,0) 2(0.5,0)
  body extent -0.55,-0.35 0.55,0.35, height 0.4
ECWFD_1260x650x1270 [mm] "TH, 2-Leads, Body 12.6x6.5mm"
  round 1.4 hole 0.9: 1(-5,0) 2(5,0)
  silkscreen extent -6.32,-3.25 6.32,3.25, body extent -6.31,-3.25 6.31,3.25, height 12.71
FUSE_392 [mm] "LITTELFUSE"
  round 1.7 hole 1.05: 1(-2.54,0) 2(2.54,0)
  silkscreen extent -4.32,-2.03 4.32,2.03, body extent -4.25,-2 4.25,2, height 8
IEC_HighVoltage_Small [mm]
  silkscreen extent -2.72,-2.24 2.72,2.47
IEC_HotSurface_Small [mm]
  silkscreen extent -2.72,-2.36 2.72,2.35
INF-PG-VSON-4 [mm] "VSON,2.00mm pitch,8.00mm W X 8.00mm L X 1.1mm H body"
  rect 1x1 smd paste+0 mask+0: 1(-3,-2.815) 2(-1,-2.815) 3(1,-2.815) 4(3,-2.815)
  rect 7.2x4.75 smd paste+0 mask+0: 5(0,2.815)
  silkscreen extent -4,-4.15 4,5.2, body extent -4,-2.8 4,5.2, height 1.01
MF05A_N [mm] "SOT23, 5-Leads, Body 2.9x1.6mm, Pitch 0.95mm, Lead Span 2.8mm, IPC Medium Density"
  rect 1.1x0.65 smd: 1(-1.2,0.95) 2(-1.2,0) 3(-1.2,-0.95) 4(1.2,-0.95) 5(1.2,0.95)
  silkscreen extent -1.33,-1.55 0.25,1.95, body extent -0.9,-1.55 0.9,1.55, height 1.19
MFP04A [mm] "FAIRCHILD optocoupler"
  rect 1.52x0.61 smd: 1(-3.175,0.635) 2(-3.175,-0.635) 3(3.175,-0.635) 4(3.175,0.635)
  silkscreen extent -2.28,-1.4 2.2,1.8, body extent -3.6,-1.34 3.6,1.34, height 2.39
Pb-Free_Overlay_Small [mm]
  silkscreen extent -1.17,-1.16 1.17,1.17
PCBComponent_1#1 [mm]
  rect 1.5x1.5 hole 0.85: 1(-4.5,0)
  round 1.5 hole 0.85: 2(4.5,0)
  silkscreen extent -5.25,-5.25 5.25,5.25
PCBComponent_1#2 [mm]
  rect 1.524x1.524 hole 0.85: 1(11.5,4.025)
  round 1.524 hole 0.85: 2(3.95,1.75)
  silkscreen extent 0,-35 14.6,0
PCBComponent_1#3 [mm]
  round 1.2 hole 0.6: 1(-2.2,0) 2(2.2,0)
  silkscreen extent -0.7,-0.2 0.7,0.2
PCBComponent_1#4 [mm]
  round 1.2 hole 0.75: 1(-3,0) 2(3,0)
  silkscreen extent -3.75,-4.47 3.75,9.02
PCBComponent_1#5 [mm]
  round 1.2 hole 0.6: 1(5,4) 2(5,-4) 3(-5,-4) 4(-5,4)
  silkscreen extent -8.5,-7.5 8.5,7.5
PG-TDSON-8 [mm] "Infineon recommended land pattern"
  rect 1.2x0.65 smd: 1(-2.825,1.905) 2(-2.825,0.635) 3(-2.825,-0.635) 4(-2.825,-1.905)
  rect 0.5x0.7 smd: 5(3.175,-2) 6(3.175,-0.675) 7(3.175,0.675) 8(3.175,2)
  rect 4.5x4.7 smd paste-2.25: 9(0.675,0)
  silkscreen extent -3.74,-3 3.74,3, body extent -3.17,-2.89 3.18,2.9, height 1.1
PQFN8_5x6 [mm] "QFN, 8-Leads, Body 5x6mm, Pitch 1.27mm"
  rect 0.775x0.6 smd: 1(-2.713,1.905) 2(-2.713,0.635) 3(-2.713,-0.635) 4(-2.713,-1.905)
  rect 0.45x0.45 smd: 5(2.7,-1.905) 6(2.7,-0.635) 7(2.7,0.635) 8(2.7,1.905)
  rect 1x1 smd: 9(-0.75,0.1)
  Top Layer region: 2.3,-2.205 3.075,-2.205 3.075,-1.605 2.775,-1.605 2.775,-0.935 3.075,-0.935 3.075,-0.335 2.775,-0.335 2.775,0.335 3.075,0.335 3.075,0.935 2.775,0.935 2.775,1.605 3.075,1.605 3.075,2.205 2.3,2.205
  Top Layer region: -1.85,-2.205 -1.85,1.68 -1.325,2.205 0.25,2.205 0.25,-2.205
  silkscreen extent -3.1,-2.6 3.1,2.6, body extent -3,-2.5 3,2.5, height 0.91
RFU02VSM6S [mm] "On Semi recommended land pattern"
  rect 1x1.4 smd: 1(1.15,0) 2(-1.15,0)
  silkscreen extent -1.75,-1.17 2.51,1.17, body extent -1.93,-0.9 1.93,0.9, height 1.35
RGE0024H [mm] "QFN, 24-Leads, Body 4x4mm, Pitch 0.5mm, Thermal Pad 2.7x2.7mm, TI Recommended"
  rrect42% 0.6x0.24 smd: 1(-1.9,1.25) 2(-1.9,0.75) 3(-1.9,0.25) 4(-1.9,-0.25) 5(-1.9,-0.75) 6(-1.9,-1.25) 13(1.9,-1.25) 14(1.9,-0.75) 15(1.9,-0.25) 16(1.9,0.25) 17(1.9,0.75) 18(1.9,1.25)
  rrect42% 0.24x0.6 smd: 7(-1.25,-1.9) 8(-0.75,-1.9) 9(-0.25,-1.9) 10(0.25,-1.9) 11(0.75,-1.9) 12(1.25,-1.9) 19(1.25,1.9) 20(0.75,1.9) 21(0.25,1.9) 22(-0.25,1.9) 23(-0.75,1.9) 24(-1.25,1.9)
  rrect50% 1.19x1.19 on Bottom Paste: 25(-0.695,-0.695) 25(-0.695,0.695) 25(0.695,-0.695) 25(0.695,0.695)
  rrect4% 2.7x2.7 smd paste-1.35: 25(0,0)
  silkscreen extent -2.22,-2.22 2.22,2.22, body extent -2.07,-2.07 2.07,2.07, height 1.01
RM4_5754 [mm] "THT, Body 11.44x11.44mm, 6Pin, Pitch 2.54mm"
  round 1.62 hole 1.02: 1(-8.525,10.975) 2(-5.95,10.975) 3(-5.95,8.5) 4(-8.525,5.925) 5(-11,5.925) 6(-11,8.5)
  silkscreen extent -13.08,-13.08 13.08,13.08
SMC [mil] "Molded Diode, 2-Leads, Body 6.9x5.8mm, IPC Medium Density, based on OnSemi component dimensions and land patterns"
  rect 110x150 smd: 1(-140.49,0) 2(140.49,0)
  silkscreen extent -221,-124 189,123, body extent -156,-116 156,116, height 91
SOD-123 [mm] "On Semi recommended land pattern"
  rect 0.915x1.22 smd: 1(-1.637,0) 2(1.637,0)
  silkscreen extent -2.74,-1.17 2.03,1.17, body extent -1.93,-0.9 1.93,0.9, height 1.35
SOD-123H [mm] "SMT, 2-Leads, Body 3.5x1.6mm"
  rect 1.3x1.8 smd: 1(-1.5,0) 2(1.5,0)
  silkscreen extent -2.9,-1.3 2.3,1.3, body extent -1.9,-0.9 1.9,0.9, height 1
SOD-123W [mm] "NXP recommended land pattern"
  rect 1.2x1.2 smd paste-0.05: 1(-1.4,0) 2(1.4,0)
  silkscreen extent -2.64,-1.14 1.68,1.14, body extent -1.85,-0.95 1.85,0.95, height 1.1
SOD-523 [mm] "NXP Semiconductor recommended land pattern, nominal STEP model"
  rect 0.8x0.6 smd paste-0.05: 1(-0.55,0) 2(0.55,0)
  silkscreen extent -1.6,-0.63 1.2,0.64, body extent -0.8,-0.4 0.8,0.4, height 0.72
SOD-523F [mm] "COMCHIP"
  rect 0.6x0.8 smd paste-0.05: 1(-0.85,0) 2(0.85,0)
  silkscreen extent -1.95,-0.9 1.1,0.9, body extent -0.9,-0.5 0.9,0.5, height 0.85
SOT-23 [mm] "SOT23, 3-Leads, Body 2.9x1.3mm, Pitch 0.95mm, Lead Span 2.5mm, IPC Medium Density"
  rrect50% 1x0.6 smd: 1(-1.2,0.95) 2(-1.2,-0.95) 3(1.2,0)
  silkscreen extent -1.62,-1.5 0.7,1.5, body extent -1.16,-1.45 1.21,1.45, height 1
SOT-223 [mm] "SOT223/SC73, 4-Leads, Body 6.5x3.5mm, Pitch 2.3mm, Lead Span 7mm, IPC Medium Density"
  rrect10% 2.4x1 smd: 1(-2.9,2.3) 2(-2.9,0) 3(-2.9,-2.3)
  rrect4% 2.4x3.3 smd: 4(2.9,0)
  silkscreen extent -3.33,-3.35 1.4,3.35, body extent -3.5,-3.25 3.5,3.25, height 1.62
SOT-323 [mm] "Zetex recommended land pattern.  March 2007"
  rect 0.8x0.6 smd: 1(-0.8,0.65) 2(-0.8,-0.65) 3(0.8,0)
  silkscreen extent -1.14,-1.22 0.77,1.22, body extent -1.13,-1.13 1.12,1.12, height 1.13
UCC28780 [mm] "Texas Insturments"
  rrect42% 0.6x0.24 smd: 1(1.4,-0.75) 2(1.4,-0.25) 3(1.4,0.25) 4(1.4,0.75) 9(-1.4,0.75) 10(-1.4,0.25) 11(-1.4,-0.25) 12(-1.4,-0.75)
  rrect42% 0.24x0.6 smd: 5(0.75,1.4) 6(0.25,1.4) 7(-0.25,1.4) 8(-0.75,1.4) 13(-0.75,-1.4) 14(-0.25,-1.4) 15(0.25,-1.4) 16(0.75,-1.4)
  rrect6% 1.68x1.68 smd paste-0.85: 17(0,0)
  rrect6% 1.55x1.55 on Bottom Paste: 17(0,0)
  silkscreen extent -1.72,-1.73 1.72,1.73, body extent -1.58,-1.58 1.57,1.57, height 0.81
WCAP-FTX2_10x6x12 [mm] "Film Capacitors, 10x6x12mm"
  round 1.4 hole 0.9: 1(-3.75,0) 2(3.75,0)
  silkscreen extent -5,-3 5,3, body extent -5,-3 5,3, height 12.05
WE-HCI_5040 [mm] "SMD, 2-Leads, Body 5.5x5.3mm"
  rect 1.6x1.9 smd: 1(0,2.05) 2(0,-2.05)
  silkscreen extent -2.65,-2.75 2.65,2.75, body extent -2.65,-2.79 2.65,2.79, height 3.95
Wurth_632_723_300_011 [mm] "Connector, Receptacle, USB Type C, R/A"
  rect 0.3x1.2 smd: A1(-2.75,10.58) A2(-2.25,10.58) A3(-1.75,10.58) A4(-1.25,10.58) A5(-0.75,10.58) A6(-0.25,10.58) A7(0.25,10.58) A8(0.75,10.58) A9(1.25,10.58) A10(1.75,10.58) A11(2.25,10.58) A12(2.75,10.58)
  round 0.55 hole 0.4: B1(2.8,9.32) B2(2.4,8.62) B3(1.6,8.62) B4(1.2,9.32) B5(0.8,8.62) B6(0.4,9.32) B7(-0.4,9.32) B8(-0.8,8.62) B9(-1.2,9.32) B10(-1.6,8.62) B11(-2.4,8.62) B12(-2.8,9.32) M1(2,9.32) M2(-2,9.32)
  rrect100% 1x1.6 hole 0.6 slot 1.2 at 90 deg: S1(-4.27,8.18) S2(-4.27,3.45) S3(4.27,3.45) S4(4.27,8.18)
  silkscreen extent -4.37,0.15 4.37,10.36, body extent -4.37,-0.96 4.37,10.83, height 3.07
Z4-D#1 [mm] "SMD, 4-Leads, Body 8.1x10.5mm"
  rect 4.7x2.4 smd: 1(-3.7,-2.55) 2(3.7,-2.55) 3(3.7,2.55) 4(-3.7,2.55)
  silkscreen extent -5.3,-4.1 5.3,4.1, body extent -5.3,-4.1 5.3,4.1, height 1.56
Z4-D#2 [mm] "SMD, 4-Leads, Body 8.1x10.5mm"
  rect 4.7x2.4 smd: 1(-3.7,2.55) 2(3.7,2.55) 3(3.7,-2.55) 4(-3.7,-2.55)
  silkscreen extent -5.3,-4.1 5.3,4.1, body extent -5.3,-4.1 5.3,4.1, height 1.56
